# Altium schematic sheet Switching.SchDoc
size A4; SheetNumber: 3; SheetTotal: 3
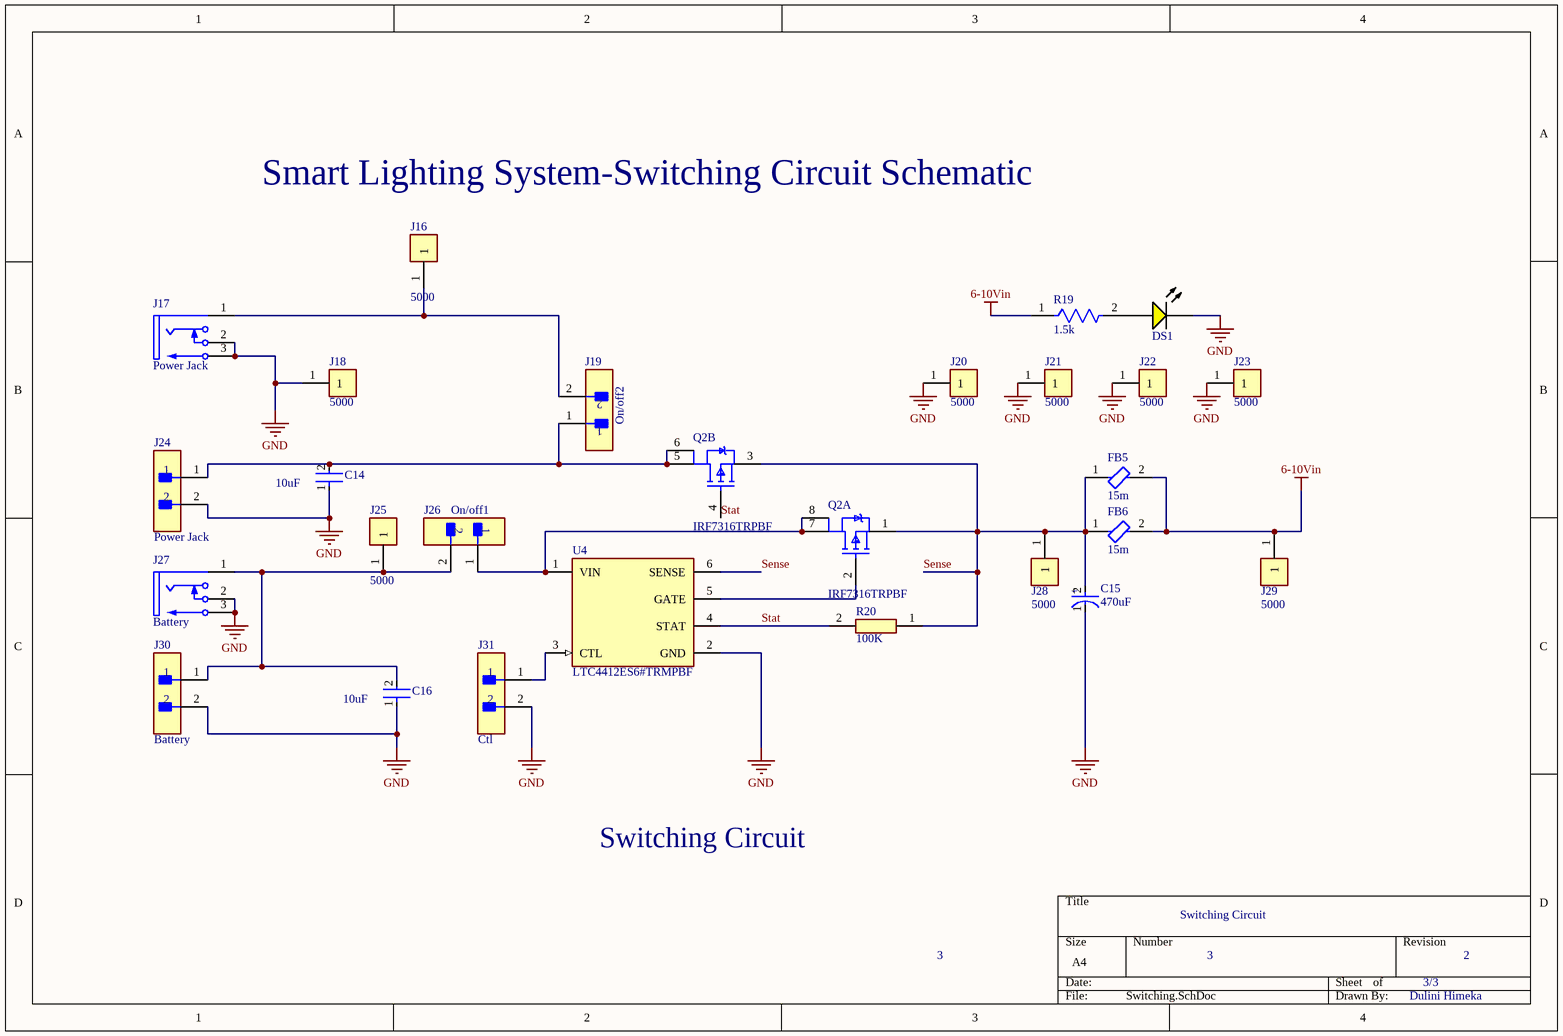
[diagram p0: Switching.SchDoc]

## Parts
C14  10uF  [FP-CL21B106KOQNNNG-MFG]
C15  470uF  [FP-FTF-MFG]
C16  10uF  [FP-CL21B106KOQNNNG-MFG]
DS1  SML-LX1206YC-TR  [LUMX-SML-LX1206YC-TR_V]  (value not drawn)
FB5  15m  [FP-BLM21-0_2-t0_85-e0_5-d-IPC_B]
FB6  15m  [FP-BLM21-0_2-t0_85-e0_5-d-IPC_B]
J16  5000  [FP-5000-MFG]
J17  Power Jack  [SWITCH-RAPC712X-3_V]
J18  5000  [FP-5000-MFG]
J19  On/off2  [FP-61900211121-MFG]
J20  5000  [FP-5000-MFG]
J21  5000  [FP-5000-MFG]
J22  5000  [FP-5000-MFG]
J23  5000  [FP-5000-MFG]
J24  Power Jack  [FP-61900211121-MFG]
J25  5000  [FP-5000-MFG]
J26  On/off1  [FP-61900211121-MFG]
J27  Battery  [SWITCH-RAPC712X-3_V]
J28  5000  [FP-5000-MFG]
J29  5000  [FP-5000-MFG]
J30  Battery  [FP-61900211121-MFG]
J31  Ctl  [FP-61900211121-MFG]
Q2  IRF7316TRPBF  [FP-PG-DSO-8-IPC_B]  (parts A,B of 2)
R19  1.5k  [FP-CRCW1206-e3-IPC_C]
R20  100K  [RESC3116X65N]
U4  LTC4412ES6#TRMPBF  [FP-S6-6-05-08-1636-IPC_C]

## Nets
6-10Vin: FB5.2 FB6.2 J29.1 R19.1
GND: C14.1 C15.1(C) C16.1 DS1.2(K) J17.2 J17.3 J18.1 J20.1 J21.1 J22.1 J23.1 J24.2 J27.2 J27.3 J30.2 J31.2 U4.2(GND)
Sense: C15.2(A) FB5.1 FB6.1 J28.1 Q2.1(S1) Q2.3(S2) R20.1 U4.6(SENSE)
Stat: Q2.4(G2) R20.2 U4.4(STAT)
NetC14_2: C14.2 J19.1 J24.1 Q2.5(D2) Q2.6(D2)
NetC16_2: C16.2 J25.1 J26.2 J27.1 J30.1
NetDS1_1: DS1.1(A) R19.2
NetJ16_1: J16.1 J17.1 J19.2
NetJ26_1: J26.1 Q2.7(D1) Q2.8(D1) U4.1(VIN)
NetJ31_1: J31.1 U4.3(CTL)
NetQ2_2: Q2.2(G1) U4.5(GATE)

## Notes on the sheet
- Smart Lighting System-Switching Circuit Schematic
- Switching Circuit
- 3
- 3/3
- 2
- Dulini Himeka

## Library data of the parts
C14 C16 = CMP-13271-000015-1: CAP CER 10UF 16V X7R 0805; Manufacturer Part Number: CL21B106KOQNNNG; Manufacturer: Samsung Electro-Mechanics; Temperature Coefficient: 15%; Tolerance: 10%; Material: Ceramic
C15 = CMP-05427-000040-1: CAP ALUM 470UF 20% 25V SMD; ESR (Equivalent Series Resistance): 80mR; Dielectric Material: Aluminium; Lead Diameter: 0.9mm; Ripple Current: 850mA; Leakage Current: 117.5uA; Life (Hours): 2000Hour
DS1 = CMP-2000-07124-1: Yellow LED, Water Clear Len, 585 nm, 2.1 V, -40 to 85 degC, 2-Pin SMD, RoHS, Tape and Reel; Manufacturer: Lumex; Product Training Modules: LEDsBenefitsofCustomLEDandLCDTechnology; Millicandela Rating: 6mcd; Catalog Drawings: SML-LX1206SeriesTopSML-LX1206SeriesSideSML-LX1206SeriesBottomSML-LX1206SeriesFootprint; Wavelength - Peak: 585nm; Other Names: 67-1358-2LU60357TRSMLLX1206YCTR; Lens Style/Size: RectanglewithFlatTop; Current - Test: 20mA; Lens Color: Colorless; Viewing Angle: 160°; Voltage - Forward (Vf) (Typ): 2.1V; Online Catalog: SML-LX1206RectanglewithFlatTop1206PackageLEDs
FB5 FB6 = CMP-06046-001820-1: Chip Ferrite Bead, 0805, 30Ω @ 100MHz, 0.014Ω, , 4A; Impedance: 30R; Shielding: Unshielded; Max DC Current: 3A; Tolerance: 25%; DC Resistance (DCR): 14mR; Material: Steel; Number of Lines: 1; DC Resistance-Max: 15MR
J16 J18 J20-J23 J25 J28 J29 = CMP-19636-000027-1: PC TEST POINT MINIATURE RED; Outside Diameter: 2.54mm; Body Material: Bronze; Number of Contacts: 1; Insulation: Insulated; Inside Diameter: 1.27mm; Hole Diameter: 1.6mm; Plating: Silver
J17 J27 = CMP-2000-05384-1: Power Jack, 5 A, 3-Pin THD, RoHS, Bulk; Manufacturer: Switchcraft; Current Rating: 5A; Plug/Mating Plug Diameter: 2.1mmID,5.5mmOD; Gender: Male; Mating Products: S765-ND / -CONNPLUGMINIPWR2CONDWHT/RED / S760K-ND / -CONNPOWERPLUGMINI.08"BLACK / SC1052-ND / -CONNPOWERPLUGMINIBLACK; Number of Positions/Contacts: 2Conductors,2Contacts; Internal Switch(s): SingleSwitch,NormallyClosed; Shielding: Unshielded; Catalog Drawings: RAPC7(1,2)2XSide / RAPC7(1,2)2XTop; Dynamic Catalog: SwitchcraftInc; Other Names: Q2287470A / RAPC722X-ND / SC1313
J19 J24 J26 J30 J31 = CMP-1502-00584-2: CONN HEADER VERT 2POS 2.54MM; Number of Contacts: 2; Gender: Male; Current Rating: 3A; Voltage Rating: 250V; Insulation Resistance: 1GR
Q2 = CMP-32901-000528-1: MOSFET 2P-CH 30V 4.9A 8-SOIC; Drain to Source Breakdown Voltage: -30V; Gate to Source Voltage (Vgs): 20V; Rise Time: 13ns; Turn-Off Delay Time: 34ns; Max Power Dissipation: 2W; Drain to Source Resistance: 98mR; Threshold Voltage: -1V; Input Capacitance: 710pF; Rds On Max: 58mR
R19 = CMP-02407-002229-1: RES Thick Film, 1.5kΩ, 1%, 0.25W, 100ppm/°C, 1206; Voltage Rating (DC): 200V; Power Rating: 250mW; Resistance: 1.5kR
R20 = CRM1206QFX-1003ELF: Resistor; Manufacturer_Name: Bourns
U4 = CMP-0479-00425-2: IC OR CTRLR SRC SELECT TSOT23-6; Min Supply Voltage: 2.5V; Max Supply Voltage: 28V; Turn-On Delay Time: 110us; Number of Channels: 1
